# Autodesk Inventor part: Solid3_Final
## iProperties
Created: 2009-02
Part Number: Solid3_Final
Document SubType Name: Modeling
Designer: Autodesk
Density: 1 g/cm^3
Author: Autodesk
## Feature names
1. TaggingFeature1
